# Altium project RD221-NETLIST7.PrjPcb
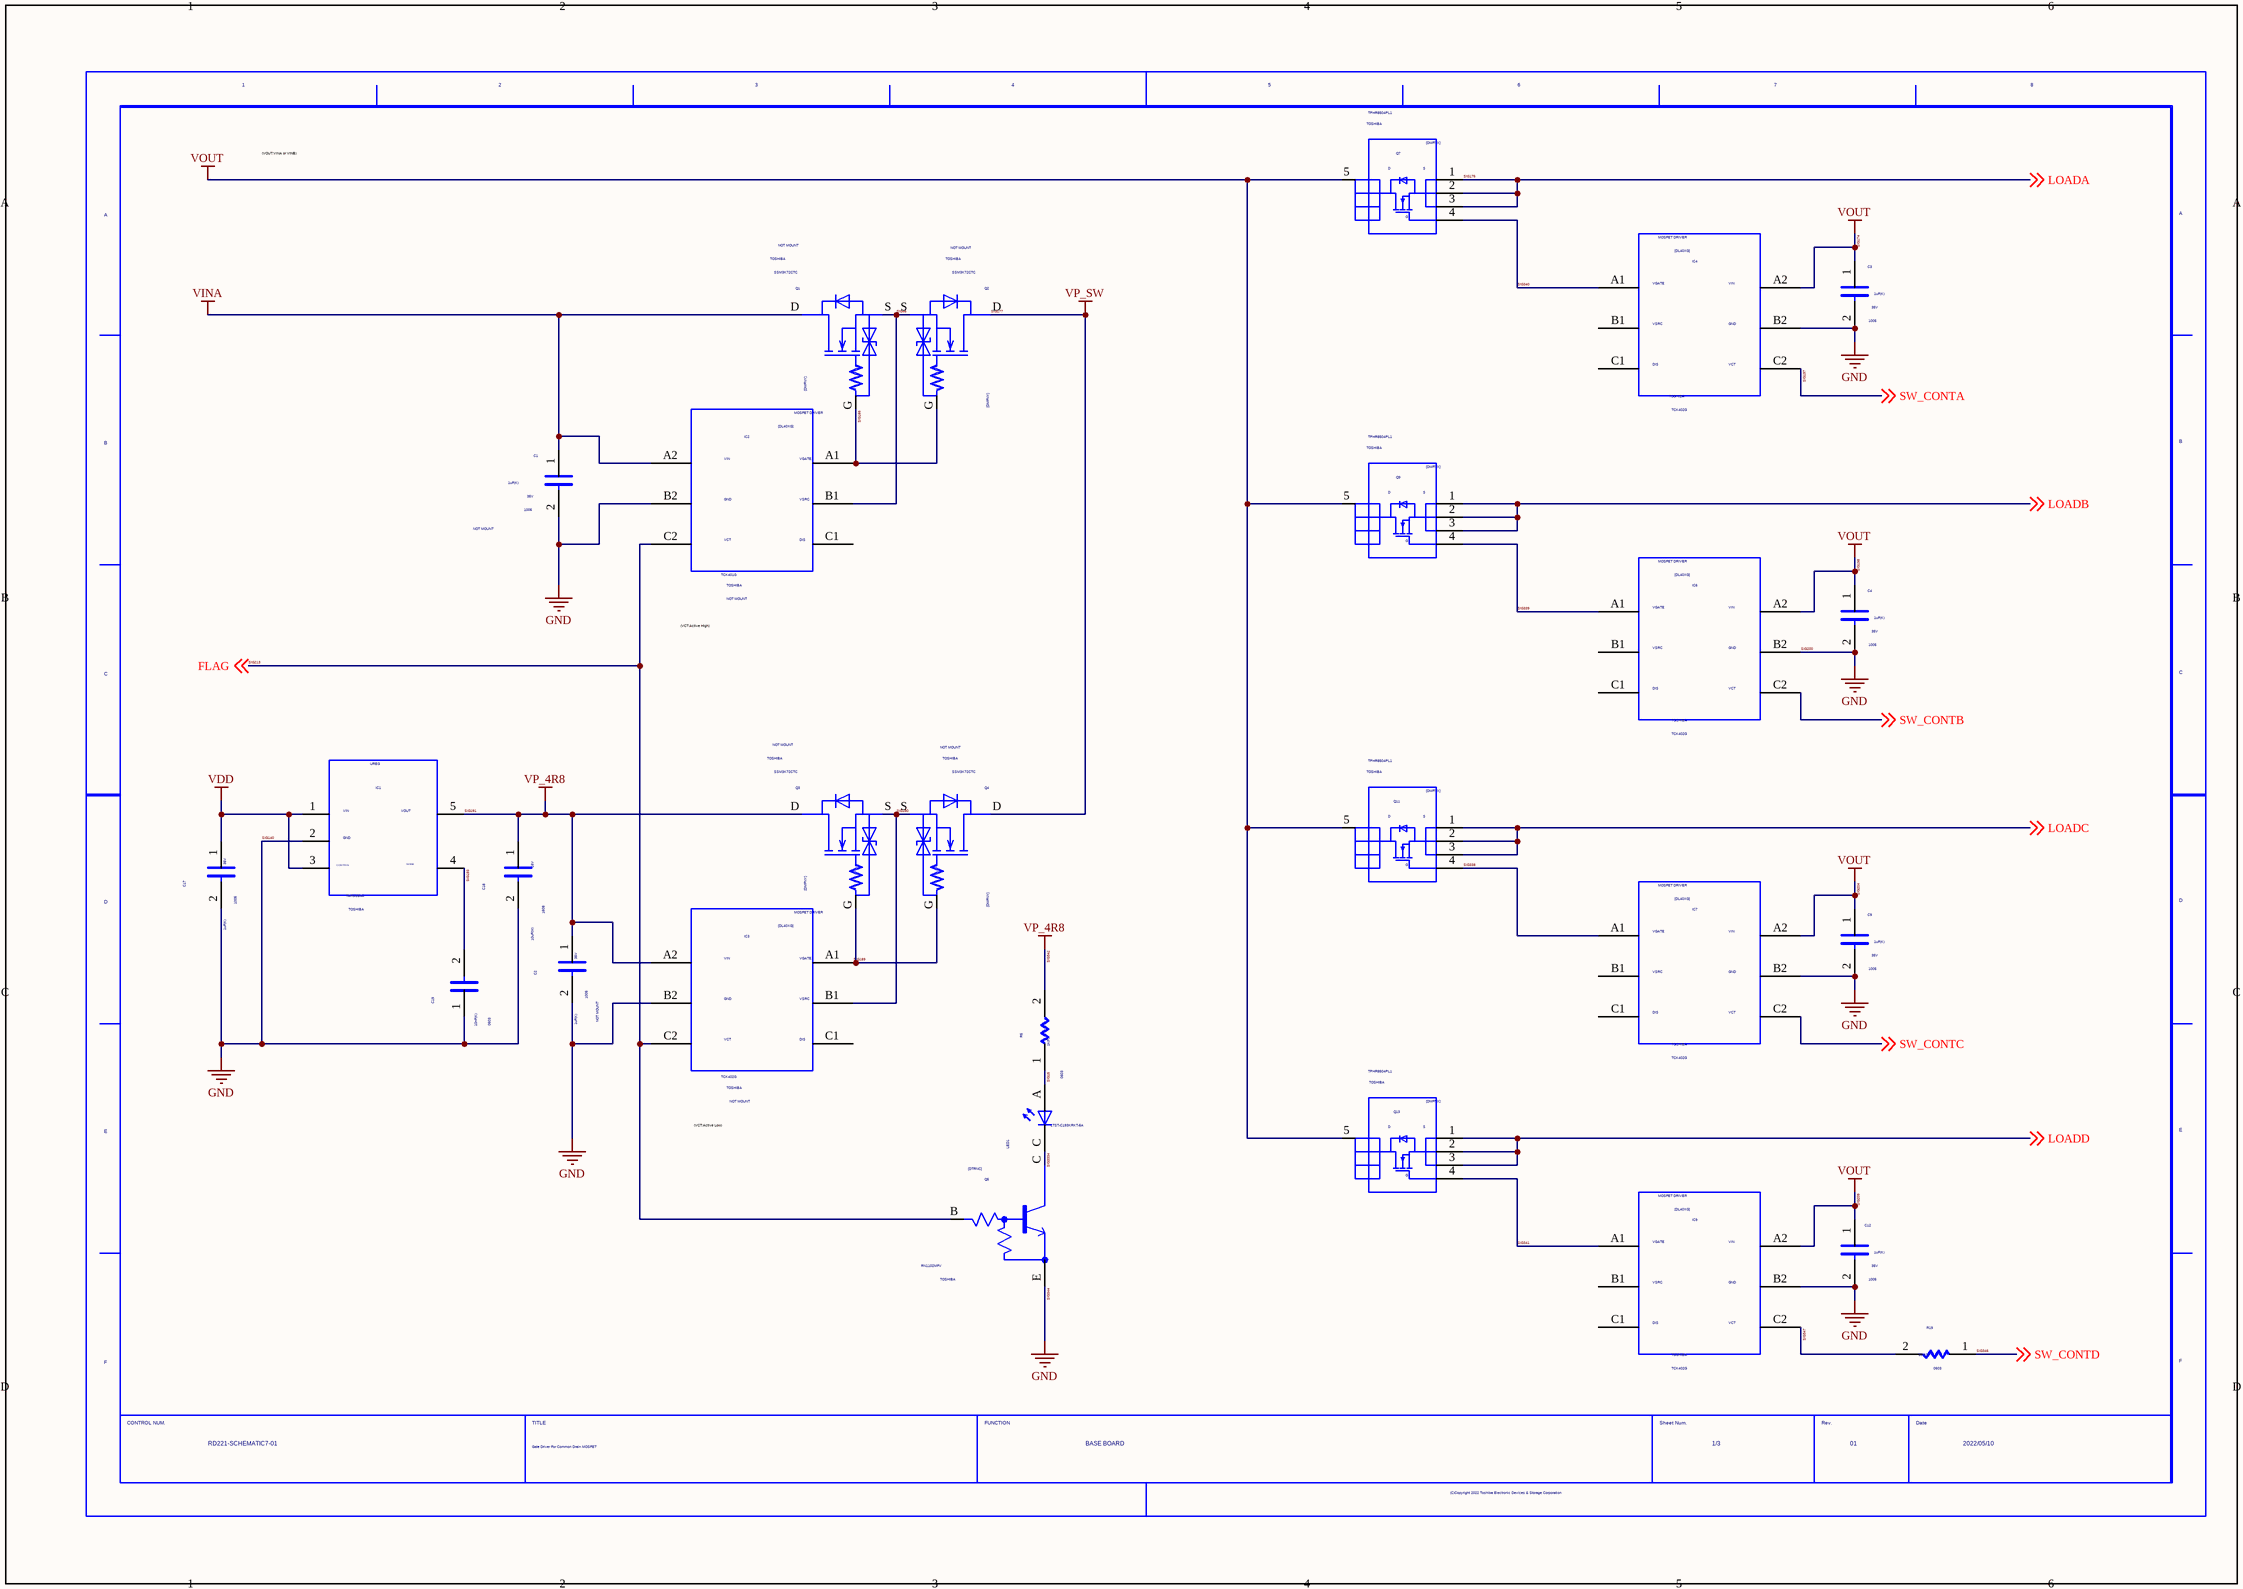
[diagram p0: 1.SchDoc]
3 sheets, 90 parts. Net scope: global (net labels, ports and power ports of the same name join across sheets).
Sheets:
  1.SchDoc
  2.SchDoc
  3.SchDoc

## Sheet 1.SchDoc
size 420 x 297 mm

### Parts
(Parts that share a designator on the sheet are numbered #1, #2 ... from top to bottom, then left to right.)
C1  NOTMOUNT: NOT MOUNT  SIZECODESMD: 1005  VAL2: 35V  VAL1: 1uF(K)  (hidden comment: DC)
C2  NOTMOUNT: NOT MOUNT  SIZECODESMD: 1005  VAL2: 35V  VAL1: 1uF(K)  (hidden comment: DC)
C3  SIZECODESMD: 1005  VAL2: 35V  VAL1: 1uF(K)  (hidden comment: DC)
C4  SIZECODESMD: 1005  VAL2: 35V  VAL1: 1uF(K)  (hidden comment: DC)
C9  SIZECODESMD: 1005  VAL2: 35V  VAL1: 1uF(K)  (hidden comment: DC)
C12  SIZECODESMD: 1005  VAL2: 35V  VAL1: 1uF(K)  (hidden comment: DC)
C17  SIZECODESMD: 1005  VAL2: 35V  VAL1: 1uF(K)  (hidden comment: DC)
C18  SIZECODESMD: 1608  VAL2: 16V  VAL1: 10uF(M)  (hidden comment: DC)
C19  SIZECODESMD: 0603  VAL1: 10nF(K)  (hidden comment: DC)
IC1  VAL1: TAR5SB48  USERCOMPTEXT3: TOSHIBA  (hidden comment: DL5SBXX)
IC2  NOTMOUNT: NOT MOUNT  VAL1: TCK401G  USERCOMPTEXT3: TOSHIBA  (hidden comment: DL40XG)
IC3  NOTMOUNT: NOT MOUNT  VAL1: TCK402G  USERCOMPTEXT3: TOSHIBA  (hidden comment: DL40XG)
IC4  VAL1: TCK402G  USERCOMPTEXT3: TOSHIBA  (hidden comment: DL40XG)
IC6  VAL1: TCK402G  USERCOMPTEXT3: TOSHIBA  (hidden comment: DL40XG)
IC7  VAL1: TCK402G  USERCOMPTEXT3: TOSHIBA  (hidden comment: DL40XG)
IC9  VAL1: TCK402G  USERCOMPTEXT3: TOSHIBA  (hidden comment: DL40XG)
LED1  VAL3: LTST-C193KRKT-5A  (hidden comment: DLED)
Q1  NOTMOUNT: NOT MOUNT  USERCOMPTEXT3: TOSHIBA  VAL1: SSM3K72CTC  (hidden comment: DMFNY)
Q2  NOTMOUNT: NOT MOUNT  USERCOMPTEXT3: TOSHIBA  VAL1: SSM3K72CTC  (hidden comment: DMFNY)
Q3  NOTMOUNT: NOT MOUNT  USERCOMPTEXT3: TOSHIBA  VAL1: SSM3K72CTC  (hidden comment: DMFNY)
Q4  NOTMOUNT: NOT MOUNT  USERCOMPTEXT3: TOSHIBA  VAL1: SSM3K72CTC  (hidden comment: DMFNY)
Q5  USERCOMPTEXT3: TOSHIBA  USERCOMPTEXT1: RN1102MFV  (hidden comment: DTRNC)
Q7  USERCOMPTEXT3: TOSHIBA  VAL1: TPHR8504PL1  (hidden comment: DMFNX)
Q9  USERCOMPTEXT3: TOSHIBA  VAL1: TPHR8504PL1  (hidden comment: DMFNX)
Q11  USERCOMPTEXT3: TOSHIBA  VAL1: TPHR8504PL1  (hidden comment: DMFNX)
Q13  USERCOMPTEXT3: TOSHIBA  VAL1: TPHR8504PL1  (hidden comment: DMFNX)
R5  SIZECODESMD: 0603  VAL1: 1k(F)  (hidden comment: DR)
R19  SIZECODESMD: 0603  VAL1: 100(J)  (hidden comment: DR)
U?#1  DATE: 2022/05/10  REVISION: 01  SHEETNUMBER: 1/3  FUNCTION: BASE BOARD  TITLE: Gate Driver For Common Drain MOSFET  DRAWINGNUMBER: RD221-SCHEMATIC7-01  (hidden comment: WAKU_DEF100)

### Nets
SIG140: C1.2 C2.2 C3.2 C4.2 C9.2 C12.2 C17.2 C18.2 C19.1 IC1.2 IC2.B2 IC3.B2 IC4.B2 IC6.B2 IC7.B2 IC9.B2 Q5.E  [also labelled GND, SIG180, SIG188, SIG200, SIG203, SIG208, SIG344]
SIG174: C3.1 C4.1 C9.1 C12.1 IC4.A2 IC6.A2 IC7.A2 IC9.A2 Q7.5 Q9.5 Q11.5 Q13.5  [also labelled SIG198, SIG204, SIG209, VOUT]
SIG177: Q2.D Q4.D  [also labelled VP_SW]
SIG187: C17.1 IC1.1 IC1.3  [also labelled VDD]
SIG191: C2.1 C18.1 IC1.5 IC3.A2 Q3.D R5.2  [also labelled SIG342, VP_4R8]
SIG213: IC2.C2 IC3.C2 Q5.B ; off-sheet FLAG  [also labelled FLAG]
VINA: C1.1 IC2.A2 Q1.D
LOADB: Q9.1 Q9.2 Q9.3 ; off-sheet LOADB
LOADC: Q11.1 Q11.2 Q11.3 ; off-sheet LOADC
LOADD: Q13.1 Q13.2 Q13.3 ; off-sheet LOADD
SIG15: LED1.A R5.1
SIG46: IC2.B1 Q1.S Q2.S
SIG166: IC2.A1 Q1.G Q2.G
SIG175: Q7.1 Q7.2 Q7.3 ; off-sheet LOADA  [also labelled LOADA]
SIG189: IC3.A1 Q3.G Q4.G
SIG190: IC3.B1 Q3.S Q4.S
SIG193: C19.2 IC1.4
SIG197: IC4.C2 ; off-sheet SW_CONTA  [also labelled SW_CONTA]
SIG338: IC7.A1 Q11.4
SIG339: IC6.A1 Q9.4
SIG340: IC4.A1 Q7.4
SIG341: IC9.A1 Q13.4
SIG346: R19.1 ; off-sheet SW_CONTD  [also labelled SW_CONTD]
SIG347: IC9.C2 R19.2
SIG3334: LED1.C Q5.C
SW_CONTB: IC6.C2 ; off-sheet SW_CONTB
SW_CONTC: IC7.C2 ; off-sheet SW_CONTC

Not connected (* = marked no-connect by the designer): IC2 C1; IC3 C1; IC4 B1 C1; IC6 B1 C1; IC7 B1 C1; IC9 B1 C1

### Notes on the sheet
- (VOUT:VINA or VINB)
- (VCT:Active High)
- (VCT:Active Low)

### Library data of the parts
C1-C4 C9 C12 C17 = DC: OUMEPARTTYPE: C; OriginalSymbolOrigin: (2540,7620); FUNCN: DP0000016125; COMPONENTNAME: DP0000016125_package; MAXGCOUNT: 1; VAL3: GRM155R6YA105KE11D
C18 = DC: OUMEPARTTYPE: C; OriginalSymbolOrigin: (2540,7620); COMPONENTNAME: DP0008993000_package; MAXGCOUNT: 1; COMP: DP0008993000; VAL3: GRM188R61C106MA73D
C19 = DC: OUMEPARTTYPE: C; OriginalSymbolOrigin: (2540,7620); MAXGCOUNT: 1; COMPONENTNAME: DP0000015127; VAL3: GRM033B31C103KA12D; VAL2: 16V
IC1 = DL5SBXX: OUMEPARTTYPE: IC; SAVEAREA0: -49052,-25553,79781,45765; SAVECOUNT: 22; TIME: 15:23:15; UPDATEUSER: t5459927; UPDATETIME: 15:26:52; OriginalSymbolOrigin: (5080,25400); FUNCN: DP0010569000; COMPONENTNAME: DP0010569000_package; MAXGCOUNT: 1
IC2 = DL40XG: OUMEPARTTYPE: IC; SAVEAREA0: -25087,-13639,60802,33906; TIME: 11:49:52; UPDATEUSER: t5459927; UPDATETIME: 14:00:32; SAVECOUNT: 26; OriginalSymbolOrigin: (7620,30480); FUNCN: DP0010565000; COMPONENTNAME: DP0010565000_package; MAXGCOUNT: 1
IC3 IC4 IC6 IC7 IC9 = DL40XG: OUMEPARTTYPE: IC; SAVEAREA0: -25087,-13639,60802,33906; TIME: 11:49:52; UPDATEUSER: t5459927; UPDATETIME: 14:00:32; SAVECOUNT: 26; OriginalSymbolOrigin: (7620,30480); FUNCN: DP0010566000; COMPONENTNAME: DP0010566000_package; MAXGCOUNT: 1
LED1 = DLED: OUMEPARTTYPE: DS; SAVEAREA0: -6799,-183,19247,15664; TIME: 14:49:55; UPDATEUSER: fukuda-y; UPDATETIME: 13:54:07; SAVECOUNT: 4; OriginalSymbolOrigin: (5080,7620); COMPONENTNAME: DP0010573000_package; MAXGCOUNT: 1; COMP: DP0010573000
Q1-Q4 = DMFNY: PARTS: 1; OUMEPARTTYPE: Q; SAVECOUNT: 28; SAVEAREA0: -23889,-10269,46852,25387; TIME: 08:01:03; UPDATEUSER: w90028dm; UPDATETIME: 15:04:53; HETERO: RN4905_1,RN4905_2; FUNCTION: PNP&NPN_PCT; LEVEL: STD; PKG_TYPE: 2-2J1A; DEVICE: RN4905; DEVICENAME: RN49A1FE(TE85L); OriginalSymbolOrigin: (2540,15240); COMPONENTNAME: DP0010564000_package; COMP: DP0010564000
Q5 = DTRNC: OUMEPARTTYPE: Q; SAVEAREA0: -25957,-6856,48160,30039; TIME: 14:43:11; UPDATEUSER: w90028dm; UPDATETIME: 10:13:46; SAVECOUNT: 5; OriginalSymbolOrigin: (2540,22860); COMPONENTNAME: DP0010015000_package; MAXGCOUNT: 1; COMP: DP0010015000; VAL3: RN1114MFV
Q7 Q9 Q11 Q13 = DMFNX: OUMEPARTTYPE: Q; SAVEAREA0: -12700,-263,35150,23556; TIME: 18:57:44; UPDATEUSER: 19990028; UPDATETIME: 11:40:13; SAVECOUNT: 15; OriginalSymbolOrigin: (5080,20320); COMPONENTNAME: DP0010567000_package; MAXGCOUNT: 1; COMP: DP0010567000
R5 = DR: OUMEPARTTYPE: R; OriginalSymbolOrigin: (5080,5080); MAXGCOUNT: 1; COMPONENTNAME: DP0000152048; VAL3: ERJ1GNF1001C; VAL2: 50mW
R19 = DR: OUMEPARTTYPE: R; OriginalSymbolOrigin: (5080,5080); MAXGCOUNT: 1; COMPONENTNAME: DP0000155000_package; COMP: DP0000155000; VAL3: RK73B1HTTC101J; VAL2: 50mW
U?#1 = WAKU_DEF100: PLOTTIME: HH:MM; SAVEAREA0: 148187,-66180,486823,89919; TIME: 14:30:25; UPDATEUSER: t5459927; UPDATETIME: 07:15:59; SAVECOUNT: 6; OriginalSymbolOrigin: (10160,284480)

## Sheet 2.SchDoc
size 420 x 297 mm
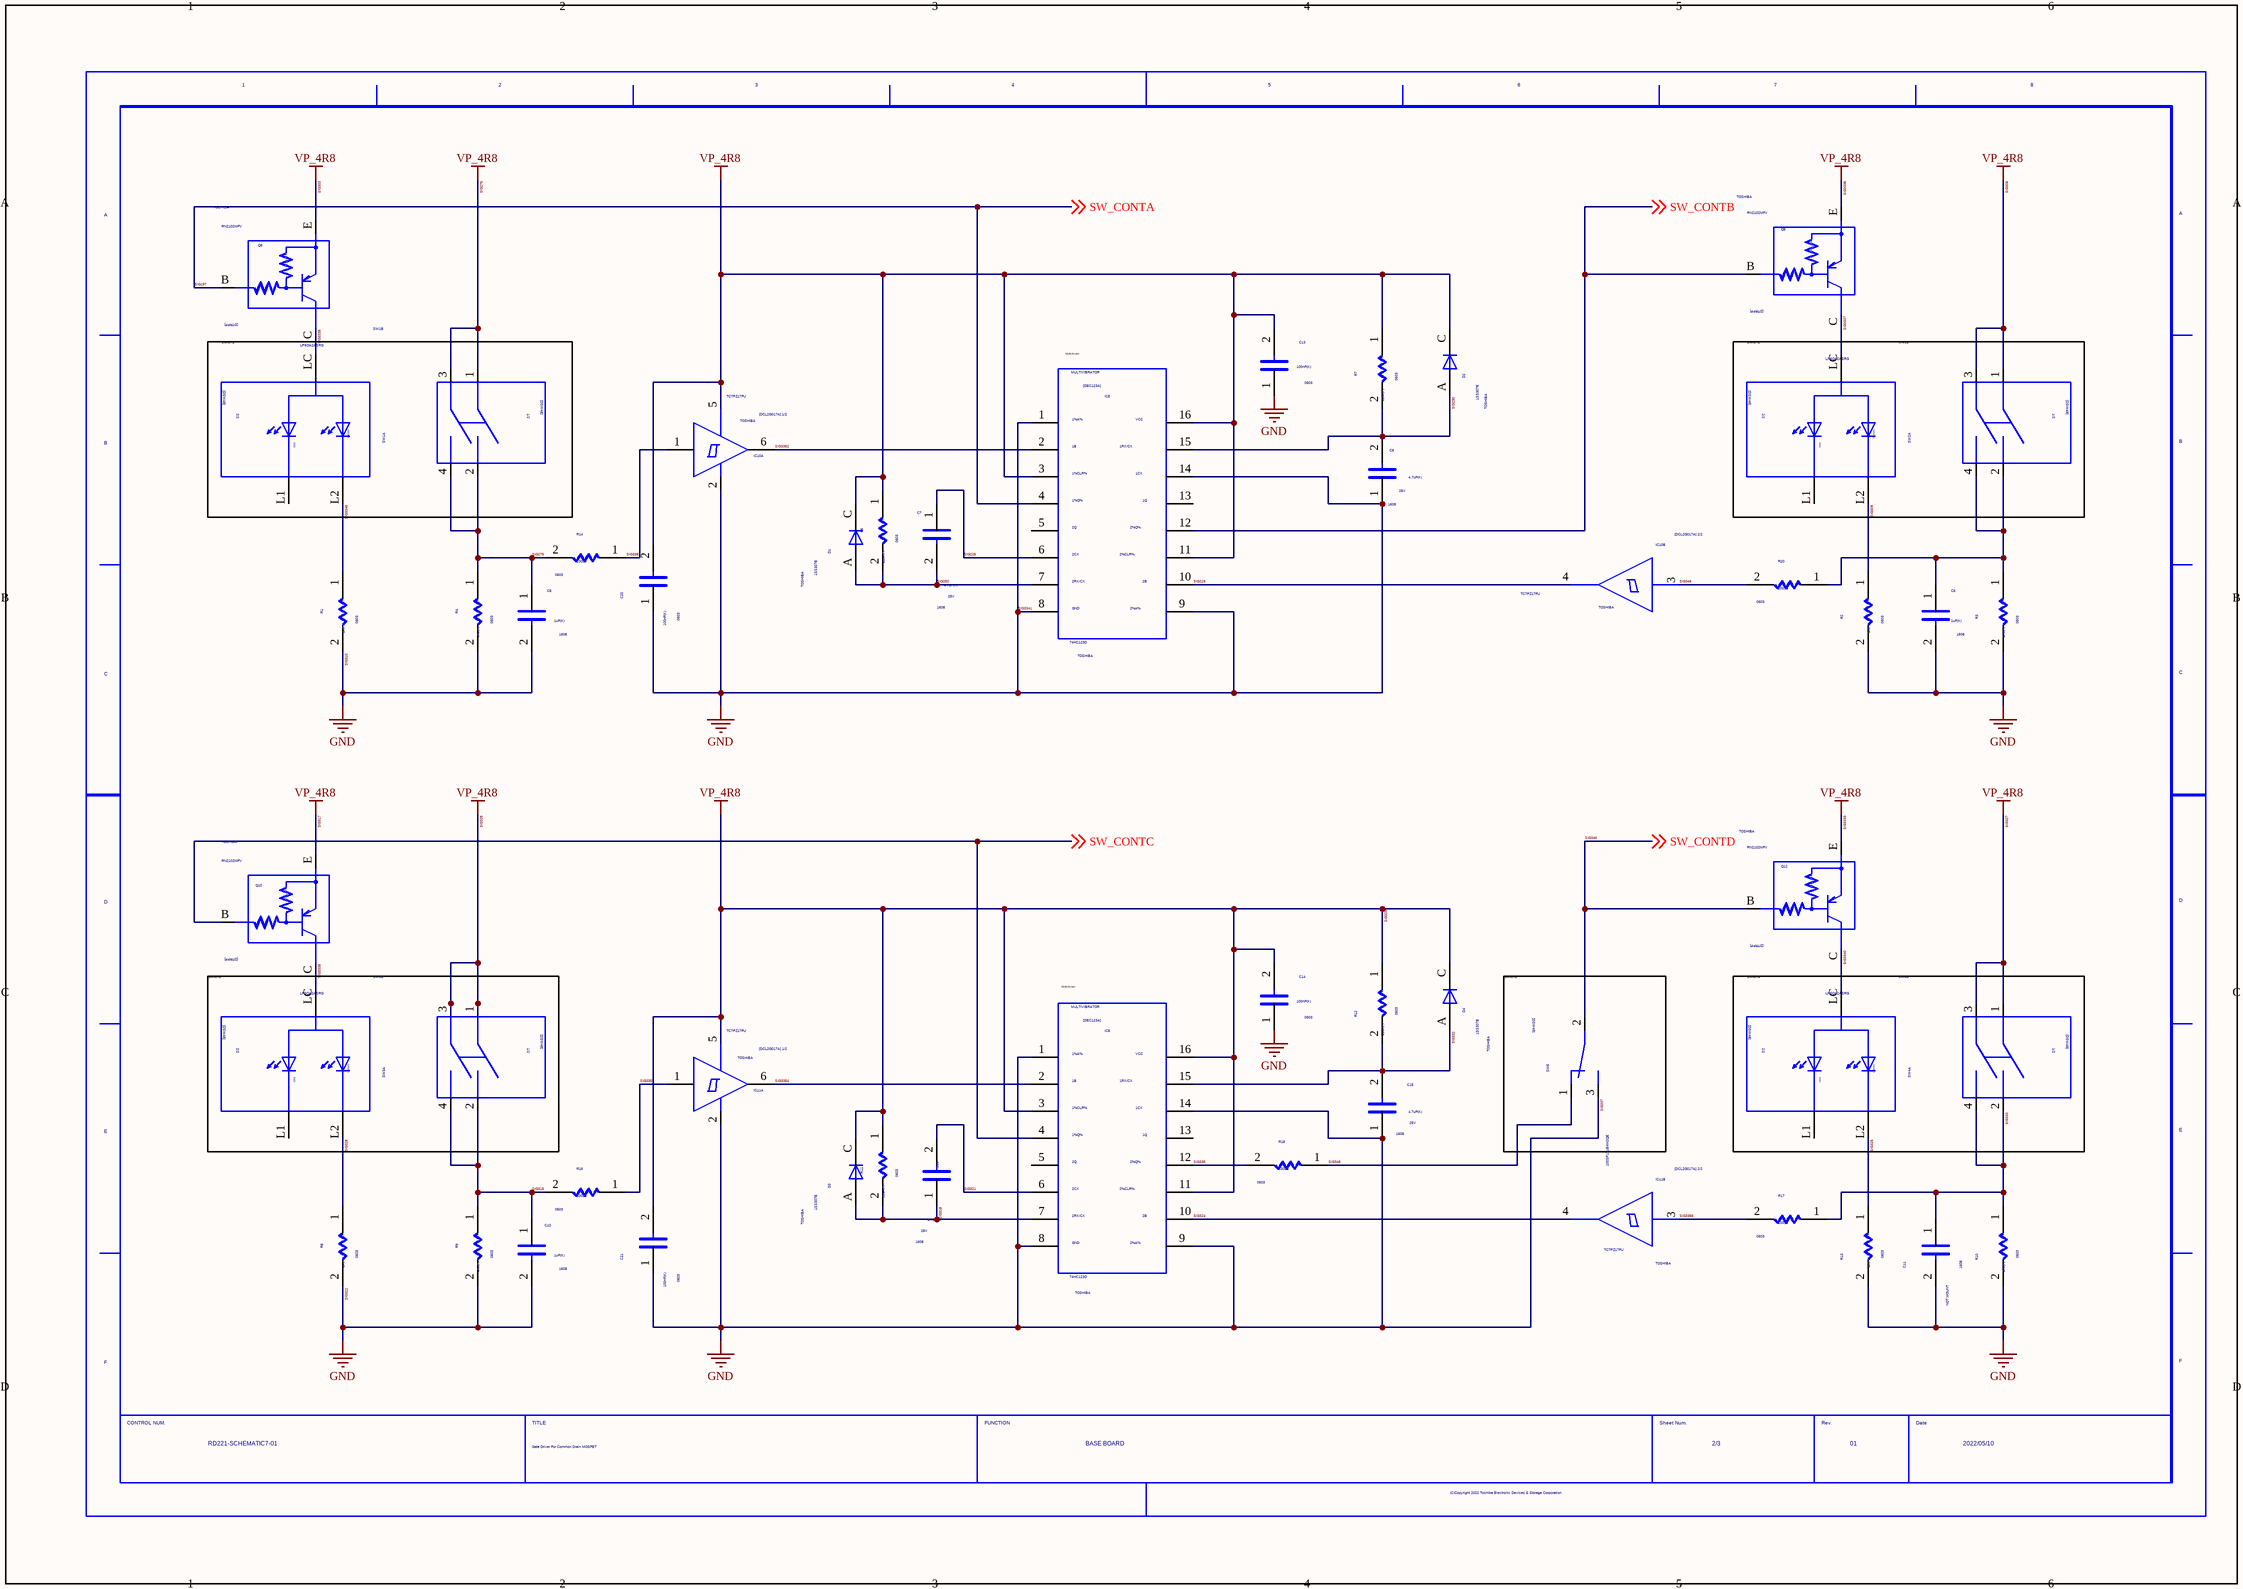
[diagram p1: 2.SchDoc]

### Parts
(Parts that share a designator on the sheet are numbered #1, #2 ... from top to bottom, then left to right.)
C5  SIZECODESMD: 1608  VAL1: 1uF(K)  (hidden comment: DC)
C6  SIZECODESMD: 1608  VAL1: 1uF(K)  (hidden comment: DC)
C7  SIZECODESMD: 1608  VAL2: 25V  VAL1: 4.7uF(K)  (hidden comment: DC)
C8  SIZECODESMD: 1608  VAL2: 25V  VAL1: 4.7uF(K)  (hidden comment: DC)
C10  SIZECODESMD: 1608  VAL1: 1uF(K)  (hidden comment: DC)
C11  NOTMOUNT: NOT MOUNT  SIZECODESMD: 1608  (hidden comment: DC)
C13  SIZECODESMD: 0603  VAL1: 100nF(K)  (hidden comment: DC)
C14  SIZECODESMD: 0603  VAL1: 100nF(K)  (hidden comment: DC)
C15  SIZECODESMD: 1608  VAL2: 25V  VAL1: 4.7uF(K)  (hidden comment: DC)
C16  SIZECODESMD: 1608  VAL2: 25V  VAL1: 4.7uF(K)  (hidden comment: DC)
C20  SIZECODESMD: 0603  VAL1: 100nF(K)  (hidden comment: DC)
C21  SIZECODESMD: 0603  VAL1: 100nF(K)  (hidden comment: DC)
D1  USERCOMPTEXT3: TOSHIBA  VAL1: 1SS307E  (hidden comment: DD)
D2  USERCOMPTEXT3: TOSHIBA  VAL1: 1SS307E  (hidden comment: DD)
D3  USERCOMPTEXT3: TOSHIBA  VAL1: 1SS307E  (hidden comment: DD)
D4  USERCOMPTEXT3: TOSHIBA  VAL1: 1SS307E  (hidden comment: DD)
IC5  USERCOMPTEXT3: TOSHIBA  VAL1: 74HC123D  (hidden comment: DEC123A)
IC8  USERCOMPTEXT3: TOSHIBA  VAL1: 74HC123D  (hidden comment: DEC123A)
IC10  USERCOMPTEXT3: TOSHIBA  VAL3: TC7PZ17FU  (hidden comment: DCL2G017A_1)  (parts A,B of 2)
IC11  USERCOMPTEXT3: TOSHIBA  VAL3: TC7PZ17FU  (hidden comment: DCL2G017A_1)  (parts A,B of 2)
Q6  USERCOMPTEXT3: TOSHIBA  VAL1: RN2102MFV  (hidden comment: DTRPF)
Q8  USERCOMPTEXT3: TOSHIBA  VAL1: RN2102MFV  (hidden comment: DTRPF)
Q10  USERCOMPTEXT3: TOSHIBA  VAL1: RN2102MFV  (hidden comment: DTRPF)
Q12  USERCOMPTEXT3: TOSHIBA  VAL1: RN2102MFV  (hidden comment: DTRPF)
R1  SIZECODESMD: 0603  VAL1: 1k(F)  (hidden comment: DR)
R2  SIZECODESMD: 0603  VAL1: 1k(F)  (hidden comment: DR)
R3  SIZECODESMD: 0603  VAL1: 47k(F)  (hidden comment: DR)
R4  SIZECODESMD: 0603  VAL1: 47k(F)  (hidden comment: DR)
R6  SIZECODESMD: 0603  VAL1: 220k(F)  (hidden comment: DR)
R7  SIZECODESMD: 0603  VAL1: 220k(F)  (hidden comment: DR)
R8  SIZECODESMD: 0603  VAL1: 1k(F)  (hidden comment: DR)
R9  SIZECODESMD: 0603  VAL1: 47k(F)  (hidden comment: DR)
R10  SIZECODESMD: 0603  VAL1: 47k(F)  (hidden comment: DR)
R11  SIZECODESMD: 0603  VAL1: 220k(F)  (hidden comment: DR)
R12  SIZECODESMD: 0603  VAL1: 220k(F)  (hidden comment: DR)
R13  SIZECODESMD: 0603  VAL1: 1k(F)  (hidden comment: DR)
R14  SIZECODESMD: 0603  VAL1: 100(J)  (hidden comment: DR)
R16  SIZECODESMD: 0603  VAL1: 100(J)  (hidden comment: DR)
R17  SIZECODESMD: 0603  VAL1: 100(J)  (hidden comment: DR)
R18  SIZECODESMD: 0603  VAL1: 100(J)  (hidden comment: DR)
R20  SIZECODESMD: 0603  VAL1: 100(J)  (hidden comment: DR)
SW1  DSW48_1  (value not drawn)  (parts A,B of 2)
SW2  DSW48_1  (value not drawn)  (parts A,B of 2)
SW3  DSW48_1  (value not drawn)  (parts A,B of 2)
SW4  DSW48_1  (value not drawn)  (parts A,B of 2)
SW5  VAL3: 100SP1T1B4M2QE  (hidden comment: DSW49)
U?#2  DATE: 2022/05/10  DRAWINGNUMBER: RD221-SCHEMATIC7-01  REVISION: 01  FUNCTION: BASE BOARD  SHEETNUMBER: 2/3  TITLE: Gate Driver For Common Drain MOSFET  (hidden comment: WAKU_DEF100)

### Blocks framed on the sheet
Switch1: SW1
Switch2: SW2
Switch3: SW3
Switch5: SW5
Switch4: SW4

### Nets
GND: C5.2 C6.2 C8.1 C10.2 C11.2 C13.1 C14.1 C15.1 C20.1 C21.1 IC5.1 IC5.8 IC5.9 IC5.14 IC8.1 IC8.8 IC8.9 IC8.14 IC10.2 IC11.2 R1.2 R2.2 R3.2 R4.2 R8.2 R9.2 R10.2 R13.2 SW5.3  [also labelled SIG310, SIG312, SIG322, SIG3341, SIG336, SIG337]  [project net SIG140]
SIG276: C13.2 C14.2 C20.2 C21.2 D1.C D2.C D3.C D4.C IC5.3 IC5.11 IC5.16 IC8.3 IC8.11 IC8.16 IC10.5 IC11.5 Q6.E Q8.E Q10.E Q12.E R6.1 R7.1 R11.1 R12.1 SW1.1 SW1.3 SW2.1 SW2.3 SW3.1 SW3.3 SW4.1 SW4.3  [also labelled SIG303, SIG308, SIG317, SIG325, SIG327, SIG329, SIG3336, SIG3339, VP_4R8]  [project net SIG191]
SIG197: IC5.4 Q6.B ; off-sheet SW_CONTA  [also labelled SW_CONTA]
SIG225: C7.1 IC5.6
SIG229: IC5.10 IC10.4
SIG230: C8.2 D2.A IC5.15 R7.2
SIG250: C7.2 D1.A IC5.7 R6.2
SIG275: C5.1 R4.1 R14.2 SW1.2 SW1.4
SIG309: R2.1 SW2.L2
SIG313: C6.1 R3.1 R20.1 SW2.2 SW2.4
SIG315: C10.1 R9.1 R16.2 SW3.2 SW3.4
SIG318: C16.1 D3.A IC8.7 R11.2
SIG321: C16.2 IC8.6
SIG324: IC8.10 IC11.4
SIG326: R13.1 SW4.L2
SIG328: R8.1 SW3.L2
SIG332: C15.2 D4.A IC8.15 R12.2
SIG333: C11.1 R10.1 R17.1 SW4.2 SW4.4
SIG335: IC8.12 R18.2
SIG345: IC10.3 R20.2
SIG346: Q12.B SW5.2 ; off-sheet SW_CONTD  [also labelled SW_CONTD]
SIG348: R18.1 SW5.1
SIG3335: Q6.C SW1.LC
SIG3337: Q8.C SW2.LC
SIG3338: Q10.C SW3.LC
SIG3340: Q12.C SW4.LC
SIG3348: R1.1 SW1.L2
SIG3352: IC5.2 IC10.6
SIG3353: IC10.1 R14.1
SIG3354: IC8.2 IC11.6
SIG3355: IC11.1 R16.1
SIG3356: IC11.3 R17.2
SW_CONTB: IC5.12 Q8.B ; off-sheet SW_CONTB
SW_CONTC: IC8.4 Q10.B ; off-sheet SW_CONTC

Not connected (* = marked no-connect by the designer): IC5 5 13; IC8 5 13; SW1 L1; SW2 L1; SW3 L1; SW4 L1

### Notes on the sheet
- Multivibrator

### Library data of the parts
C5 C6 C10 = DC: OUMEPARTTYPE: C; OriginalSymbolOrigin: (2540,7620); MAXGCOUNT: 1; COMPONENTNAME: DP0000149011_package; COMP: DP0000149011; VAL3: GMK107BJ105KA-T; VAL2: 35V
C7 C8 C15 C16 = DC: OUMEPARTTYPE: C; OriginalSymbolOrigin: (2540,7620); COMPONENTNAME: DP0000017116_package; MAXGCOUNT: 1; COMP: DP0000017116; VAL3: GRM188R61E475KE15D
C11 = DC: OUMEPARTTYPE: C; OriginalSymbolOrigin: (2540,7620); MAXGCOUNT: 1; COMPONENTNAME: DP0000149011_package; COMP: DP0000149011; VAL3: GMK107BJ105KA-T; VAL2: 35V; VAL1: 1uF(K)
C13 C14 C20 C21 = DC: OUMEPARTTYPE: C; OriginalSymbolOrigin: (2540,7620); MAXGCOUNT: 1; COMPONENTNAME: DP0000015406_package; COMP: DP0000015406; VAL3: GRM033R61C104KE14D; VAL2: 16V
D1-D4 = DD: OUMEPARTTYPE: D; SAVEAREA0: -225,-91,12804,7836; SAVECOUNT: 3; TIME: 14:49:55; UPDATEUSER: 19870035; UPDATETIME: 14:20:16; OriginalSymbolOrigin: (5080,5080); COMPONENTNAME: DP0005002000_package; MAXGCOUNT: 1; COMP: DP0005002000
IC5 IC8 = DEC123A: OUMEPARTTYPE: IC; SAVEAREA0: -51950,-1012,82634,54279; SAVECOUNT: 6; TIME: 14:53:14; UPDATEUSER: w90028dm; UPDATETIME: 14:48:13; OriginalSymbolOrigin: (5080,50800); COMPONENTNAME: DP0010568000_package; MAXGCOUNT: 1; COMP: DP0010568000
IC10 IC11 = DCL2G017A_1: OUMEPARTTYPE: IC; TIME: 14:48:25; UPDATEUSER: w90028dm; UPDATETIME: 11:00:47; SAVECOUNT: 12; SAVEAREA0: -27668,-19920,47920,35415; OriginalSymbolOrigin: (0,12700); CaptureCellPackProp: DCL2G017A_1A; COMPONENTNAME: DCL2G017A_pinAssign_DCL2G017A_1_function; MAXGCOUNT: 1; COMP: DP0010608000; FUNCN: DCL2G017A_1_function
Q6 Q8 Q10 Q12 = DTRPF: PARTS: 1; OUMEPARTTYPE: Q; HETERO: RN4905_1,RN4905_2; FUNCTION: PNP&NPN_PCT; LEVEL: STD; PKG_TYPE: 2-2J1A; DEVICE: RN4905; SAVECOUNT: 12; SAVEAREA0: -44788,-13627,70567,33764; DEVICENAME: RN2104; TIME: 19:37:19; UPDATEUSER: w90028dm; UPDATETIME: 15:25:57; OriginalSymbolOrigin: (2540,20320); COMPONENTNAME: DP0010570000_package; COMP: DP0010570000
R1 R2 R8 R13 = DR: as R5 on sheet 1
R3 R4 R9 R10 = DR: OUMEPARTTYPE: R; OriginalSymbolOrigin: (5080,5080); MAXGCOUNT: 1; COMPONENTNAME: DP0000152088; VAL3: ERJ1GNF4702C; VAL2: 50mW
R6 R11 = DR: OUMEPARTTYPE: R; OriginalSymbolOrigin: (5080,5080); MAXGCOUNT: 1; COMPONENTNAME: DP0000152104; VAL3: ERJ1GNF2203C; VAL2: 50mW
R7 R12 = DR: OUMEPARTTYPE: R; OriginalSymbolOrigin: (5080,5080); MAXGCOUNT: 1; COMPONENTNAME: DP0000155128; VAL3: RK73B1HTTC224J; VAL2: 50mW
R14 R16-R18 R20 = DR: as R19 on sheet 1
SW1-SW4 = DSW48_1: PARTS: 1; OUMEPARTTYPE: S; SAVECOUNT: 17; SAVEAREA0: -14290,-6784,35003,29302; TIME: 19:37:19; UPDATEUSER: w90028dm; UPDATETIME: 08:14:33; OriginalSymbolOrigin: (2540,20320); HETERO: RN4905_1,RN4905_2; FUNCTION: PNP&NPN_PCT; LEVEL: STD; P/D_NUM: TOSHIBA; PKG_TYPE: 2-2J1A; DEVICE: RN4905; DEVICENAME: RN2104; CLASS: DISCRETE; CaptureCellPackProp: DSW48_1A; RATEDCURRENT: 12m; RATEDVOLTAGE: 12; COMPONENTNAME: DSW48_pinAssign_DSW48_2_function; OUMEMAKER: ZZZ ＊＊＊暫定＊＊＊; FNLEADFREETHET1GT2GMCTH1: N_N_N; OUMECLASSIFICATION: プッシュボタン／タクトスイッチ; MOUNTINGFORM: 挿入実装; COMP: DP0010571000; FUNCN: DSW48_2_function; ADSCNVFLAG: ON; OUMEMAKERKATAMEI: LP6OA2ASRG; NUMBEROFPOSITIO: 2POS
SW5 = DSW49: OUMEPARTTYPE: S; SAVEAREA0: -42205,-15236,59041,26359; TIME: 14:45:03; UPDATEUSER: w90028dm; UPDATETIME: 17:53:32; SAVECOUNT: 4; OriginalSymbolOrigin: (2540,10160); COMPONENTNAME: DP0010575000_package; MAXGCOUNT: 1; COMP: DP0010575000
U?#2 = WAKU_DEF100: PLOTTIME: HH:MM; SAVEAREA0: 148187,-66180,486823,89919; TIME: 14:30:25; UPDATEUSER: t5459927; UPDATETIME: 16:52:10; SAVECOUNT: 6; OriginalSymbolOrigin: (10160,284480)

## Sheet 3.SchDoc
size 420 x 297 mm
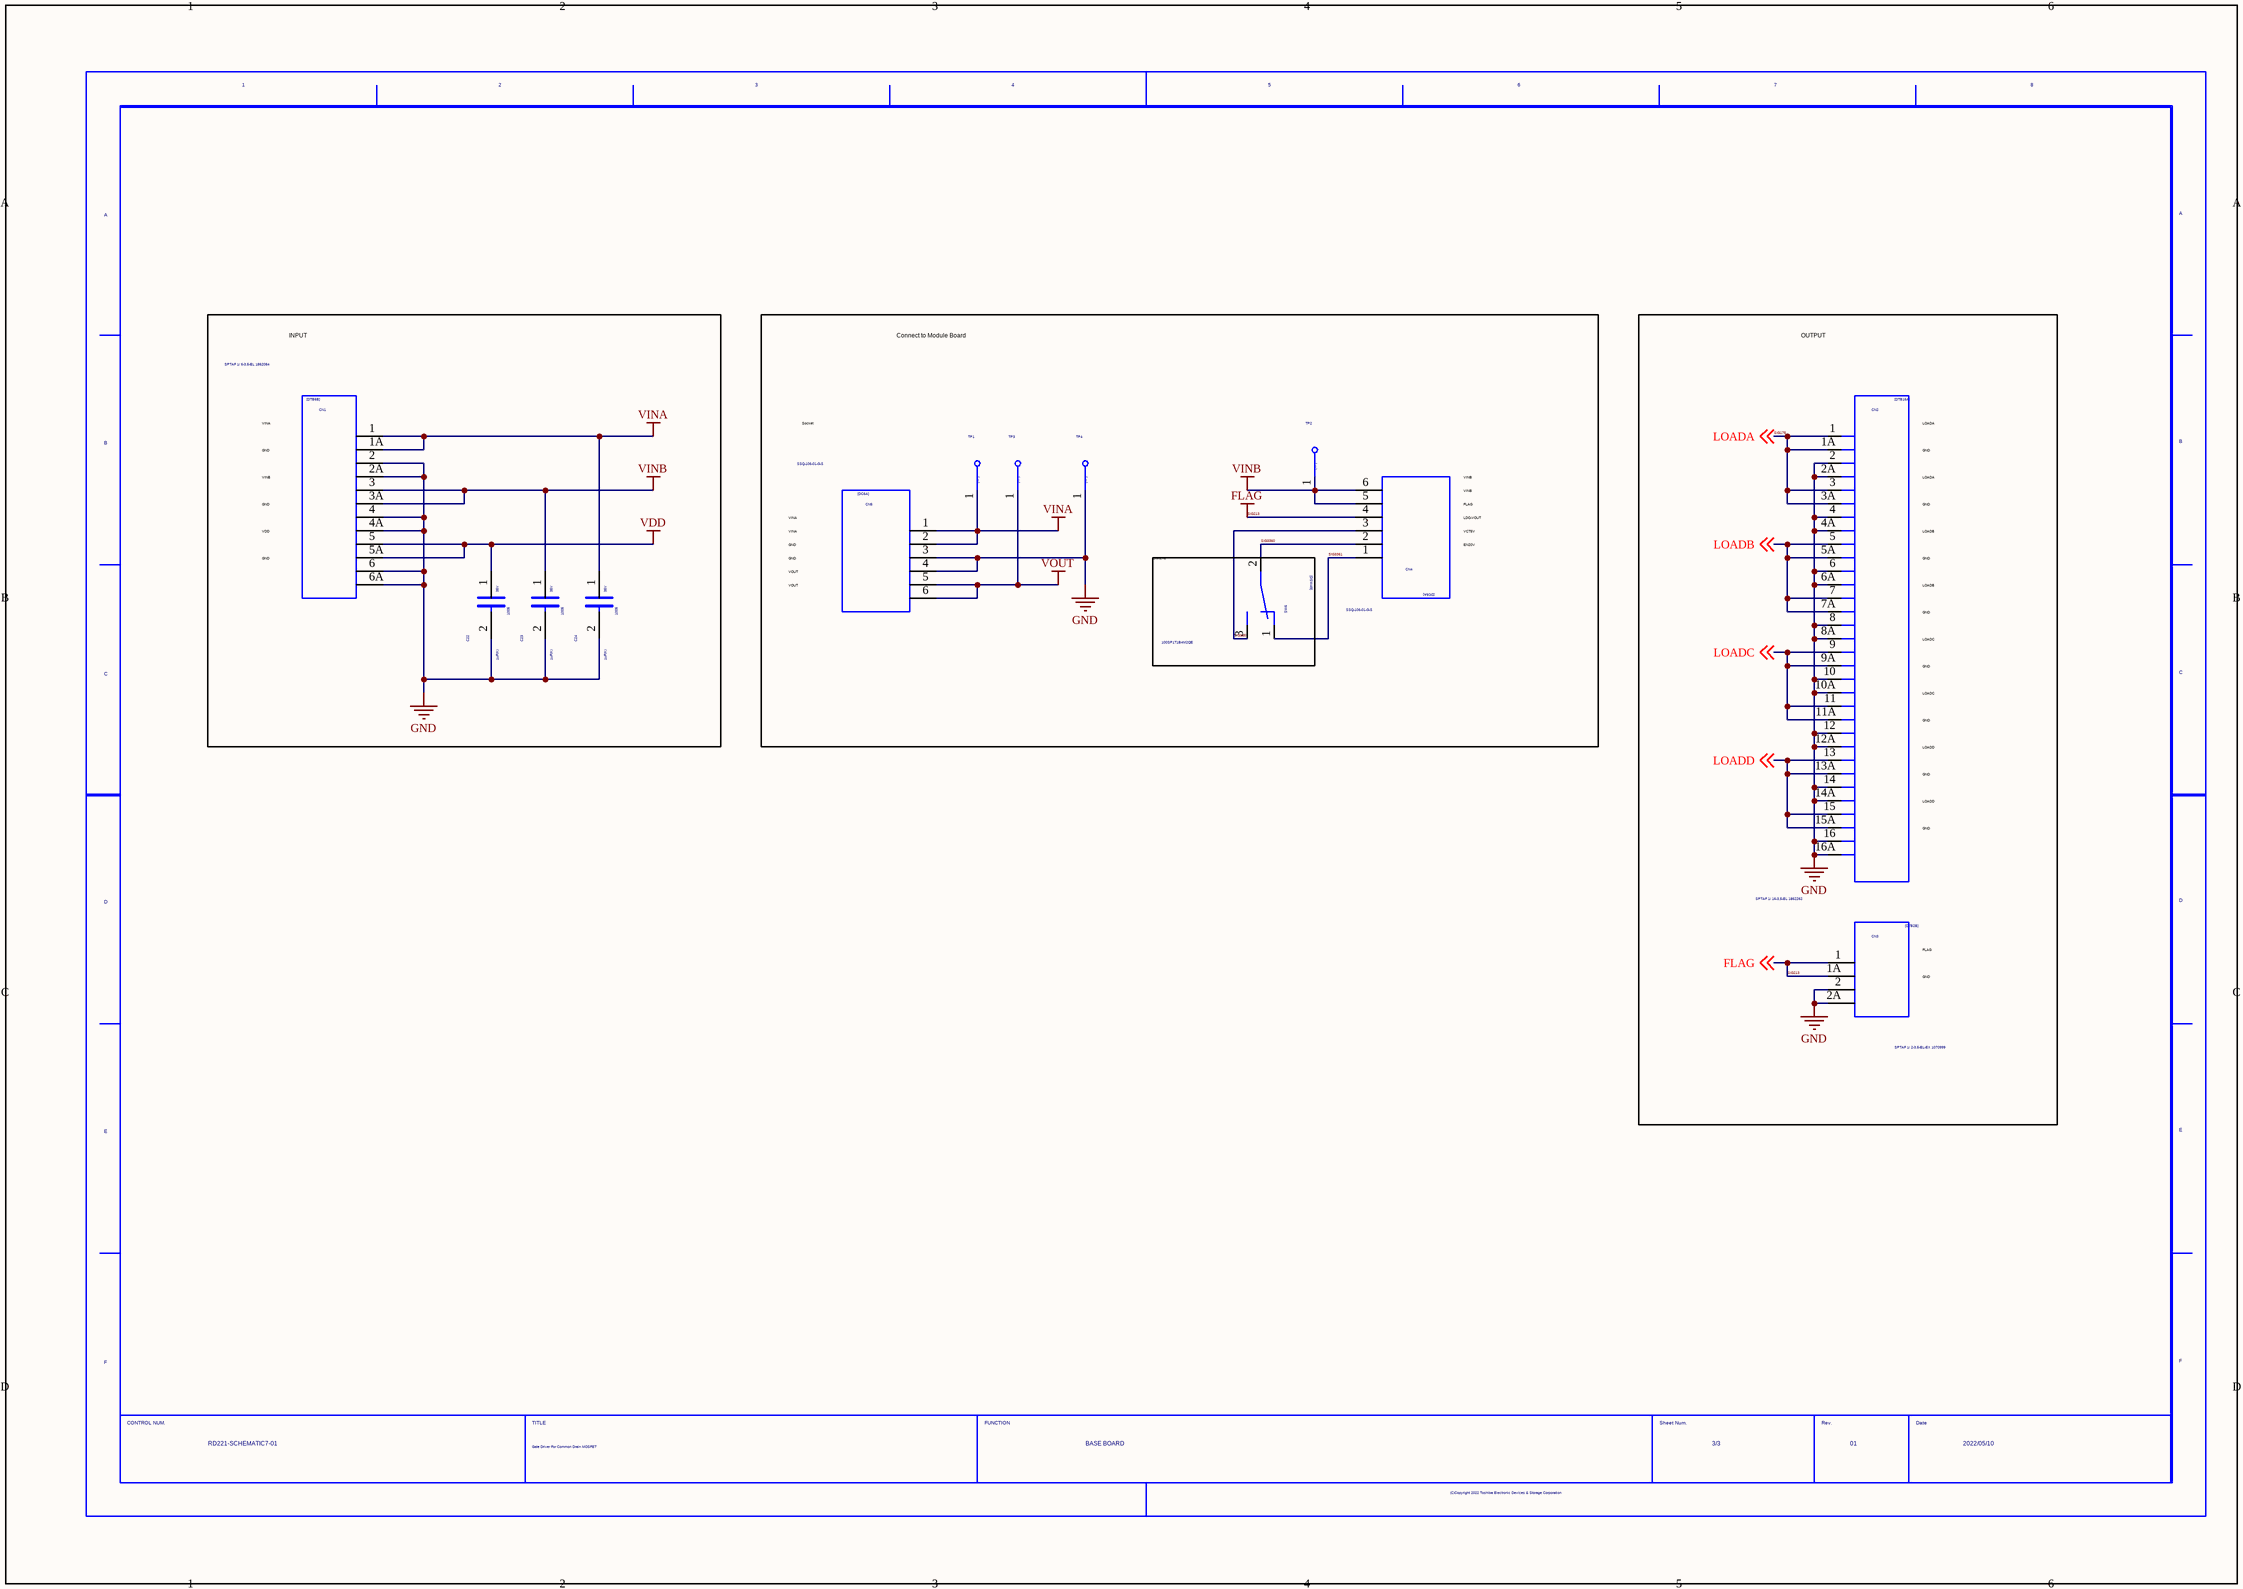
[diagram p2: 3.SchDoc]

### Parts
(Parts that share a designator on the sheet are numbered #1, #2 ... from top to bottom, then left to right.)
C22  SIZECODESMD: 1005  VAL2: 35V  VAL1: 1uF(K)  (hidden comment: DC)
C23  SIZECODESMD: 1005  VAL2: 35V  VAL1: 1uF(K)  (hidden comment: DC)
C24  SIZECODESMD: 1005  VAL2: 35V  VAL1: 1uF(K)  (hidden comment: DC)
CN1  VAL3: SPTAF 1/ 6-3,5-EL 1862084  (hidden comment: DTB6B)
CN2  VAL3: SPTAF 1/ 16-3,5-EL 1862262  (hidden comment: DTB16A)
CN3  VAL3: SPTAF 1/ 2-3,5-EL-EX 1070999  (hidden comment: DTB2B)
CN4  VAL3: SSQ-106-01-G-S  (hidden comment: DC6A)
CN5  VAL3: SSQ-106-01-G-S  (hidden comment: DC6A)
SW6  VAL3: 100SP1T1B4M2QE  (hidden comment: DSW49)
TP1  DTP  (value not drawn)
TP2  DTP  (value not drawn)
TP3  DTP  (value not drawn)
TP4  DTP  (value not drawn)
U?#3  DATE: 2022/05/10  REVISION: 01  SHEETNUMBER: 3/3  FUNCTION: BASE BOARD  TITLE: Gate Driver For Common Drain MOSFET  DRAWINGNUMBER: RD221-SCHEMATIC7-01  (hidden comment: WAKU_DEF100)

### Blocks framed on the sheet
INPUT: C22-C24 CN1
Connect to Module Board: CN4 CN5 TP1-TP4
OUTPUT: CN2 CN3
Switch6: SW6

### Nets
GND: C22.2 C23.2 C24.2 CN1.2 CN1.2A CN1.4 CN1.4A CN1.6 CN1.6A CN2.2 CN2.2A CN2.4 CN2.4A CN2.6 CN2.6A CN2.8 CN2.8A CN2.10 CN2.10A CN2.12 CN2.12A CN2.14 CN2.14A CN2.16 CN2.16A CN3.2 CN3.2A CN5.3 CN5.4 TP4.1  [project net SIG140]
SIG213: CN3.1 CN3.1A CN4.4 ; off-sheet FLAG  [also labelled FLAG]
VDD: C22.1 CN1.5 CN1.5A  [project net SIG187]
VINA: C24.1 CN1.1 CN1.1A CN5.1 CN5.2 TP1.1
VINB: C23.1 CN1.3 CN1.3A CN4.5 CN4.6 TP2.1
VOUT: CN5.5 CN5.6 TP3.1  [project net SIG174]
LOADB: CN2.5 CN2.5A CN2.7 CN2.7A ; off-sheet LOADB
LOADC: CN2.9 CN2.9A CN2.11 CN2.11A ; off-sheet LOADC
LOADD: CN2.13 CN2.13A CN2.15 CN2.15A ; off-sheet LOADD
SIG175: CN2.1 CN2.1A CN2.3 CN2.3A ; off-sheet LOADA  [also labelled LOADA]
SIG3359: CN4.3 SW6.3
SIG3360: CN4.2 SW6.2
SIG3361: CN4.1 SW6.1

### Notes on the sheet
- VINA
- GND
- Socket
- LOADA
- VINB
- VDD
- FLAG
- LDO-VOUT
- VCT5V
- LOADB
- VOUT
- EN20V
- LOADC
- LOADD

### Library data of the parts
C22-C24 = DC: OUMEPARTTYPE: C; OriginalSymbolOrigin: (2540,7620); COMPONENTNAME: DP0000016125_package; MAXGCOUNT: 1; COMP: DP0000016125; VAL3: GRM155R6YA105KE11D
CN1 = DTB6B: OUMEPARTTYPE: TB; SAVEAREA0: -69082,-11475,84961,51811; TIME: 10:12:24; UPDATEUSER: w90028dm; UPDATETIME: 11:01:53; SAVECOUNT: 6; OriginalSymbolOrigin: (0,38100); COMPONENTNAME: DP0010576000_package; MAXGCOUNT: 1; COMP: DP0010576000
CN2 = DTB16A: OUMEPARTTYPE: TB; SAVEAREA0: -110709,-1964,126601,95531; TIME: 12:01:18; UPDATEUSER: w90028dm; UPDATETIME: 09:06:25; SAVECOUNT: 20; OriginalSymbolOrigin: (0,91440); COMPONENTNAME: DP0010577000_package; MAXGCOUNT: 1; COMP: DP0010577000
CN3 = DTB2B: OUMEPARTTYPE: TB; SAVEAREA0: -49339,-13811,66103,33616; TIME: 10:12:24; UPDATEUSER: w90028dm; UPDATETIME: 11:01:13; SAVECOUNT: 5; OriginalSymbolOrigin: (0,17780); COMPONENTNAME: DP0010578000_package; MAXGCOUNT: 1; COMP: DP0010578000
CN4 CN5 = DC6A: OUMEPARTTYPE: CN; SAVEAREA0: -19103,0,39483,27940; SAVECOUNT: 24; TIME: 13:28:28; UPDATEUSER: e1023210; UPDATETIME: 18:37:18; OriginalSymbolOrigin: (2540,25400); COMPONENTNAME: DP0010574000_package; MAXGCOUNT: 1; COMP: DP0010574000
SW6 = DSW49: as SW5 on sheet 2
TP1-TP4 = DTP: OUMEPARTTYPE: TP; TIME: 16:12:21; UPDATEUSER: fukuda-y; UPDATETIME: 16:18:11; SAVECOUNT: 2; SAVEAREA0: -242,-92,12810,7836; OriginalSymbolOrigin: (0,7620); NOTMOUNT: NOT MOUNT; COMPONENTNAME: DP9000817000_package; MAXGCOUNT: 1; COMP: DP9000817000
U?#3 = WAKU_DEF100: PLOTTIME: HH:MM; SAVEAREA0: 148187,-66180,486823,89919; TIME: 14:30:25; UPDATEUSER: t5459927; UPDATETIME: 18:03:24; SAVECOUNT: 6; OriginalSymbolOrigin: (10160,284480)

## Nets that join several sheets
SIG140: 1 (17 pins), 2 (29 pins), 3 (30 pins)
SIG174: 1 (12 pins), 3 (CN5.5 CN5.6 TP3.1)
SIG187: 1 (C17.1 IC1.1 IC1.3), 3 (C22.1 CN1.5 CN1.5A)
SIG191: 1 (6 pins), 2 (32 pins)
SIG213: 1 (IC2.C2 IC3.C2 Q5.B), 3 (CN3.1 CN3.1A CN4.4)
VINA: 1 (C1.1 IC2.A2 Q1.D), 3 (6 pins)
LOADB: 1 (Q9.1 Q9.2 Q9.3), 3 (CN2.5 CN2.5A CN2.7 CN2.7A)
LOADC: 1 (Q11.1 Q11.2 Q11.3), 3 (CN2.9 CN2.9A CN2.11 CN2.11A)
LOADD: 1 (Q13.1 Q13.2 Q13.3), 3 (CN2.13 CN2.13A CN2.15 CN2.15A)
SIG175: 1 (Q7.1 Q7.2 Q7.3), 3 (CN2.1 CN2.1A CN2.3 CN2.3A)
SIG197: 1 (IC4.C2), 2 (IC5.4 Q6.B)
SIG346: 1 (R19.1), 2 (Q12.B SW5.2)
SW_CONTB: 1 (IC6.C2), 2 (IC5.12 Q8.B)
SW_CONTC: 1 (IC7.C2), 2 (IC8.4 Q10.B)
